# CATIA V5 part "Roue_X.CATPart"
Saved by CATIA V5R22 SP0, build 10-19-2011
Part number: Roue_X
Material "Antidérapant"
Bounding box of the stored display mesh (mm): x -7.5 to 7.5, y -7.312 to 7.312, z 0 to 21
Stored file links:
  U:\S9A\PER\CAO_Projet_ZG4\Cadre\Chariot_X\Roue_X.CATPart
  U:\S9A\PER\CAO_Projet_ZG4\Cadre\Chariot_X\no_skid.jpg
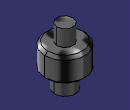
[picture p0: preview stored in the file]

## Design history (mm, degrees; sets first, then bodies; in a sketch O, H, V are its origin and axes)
Body1 (main body), material "Antidérapant"
  Sketch1 on xy-plane, origin (0, 0, 0), H (1, 0, 0), V (0, 1, 0)
    circle A1 centre (0, 0) radius 4
    radius A1 = 4
  Pad1: profile Sketch1, direction (0, 0, 1), length 6
  Sketch2 on end face of Pad1, origin (0, 0, 6), H (1, 0, 0), V (0, 1, 0)
    circle A1 centre (0, 0) radius 7.5
    radius A1 = 7.5
  Pad2: profile Sketch2, direction (0, 0, 1), length 9
  Sketch3 on end face of Pad2, origin (0, 0, 15), H (1, 0, 0), V (0, 1, 0)
    circle A1 centre (0, 0) radius 3
    radius A1 = 3
  Pad3: profile Sketch3, direction (0, 0, 1), length 6
  Chamfer1: length 1, angle 45, on edge [start face of Pad2 | face of Pad2 from Sketch2.A1]; edge [face of Pad2 from Sketch2.A1 | end face of Pad2]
